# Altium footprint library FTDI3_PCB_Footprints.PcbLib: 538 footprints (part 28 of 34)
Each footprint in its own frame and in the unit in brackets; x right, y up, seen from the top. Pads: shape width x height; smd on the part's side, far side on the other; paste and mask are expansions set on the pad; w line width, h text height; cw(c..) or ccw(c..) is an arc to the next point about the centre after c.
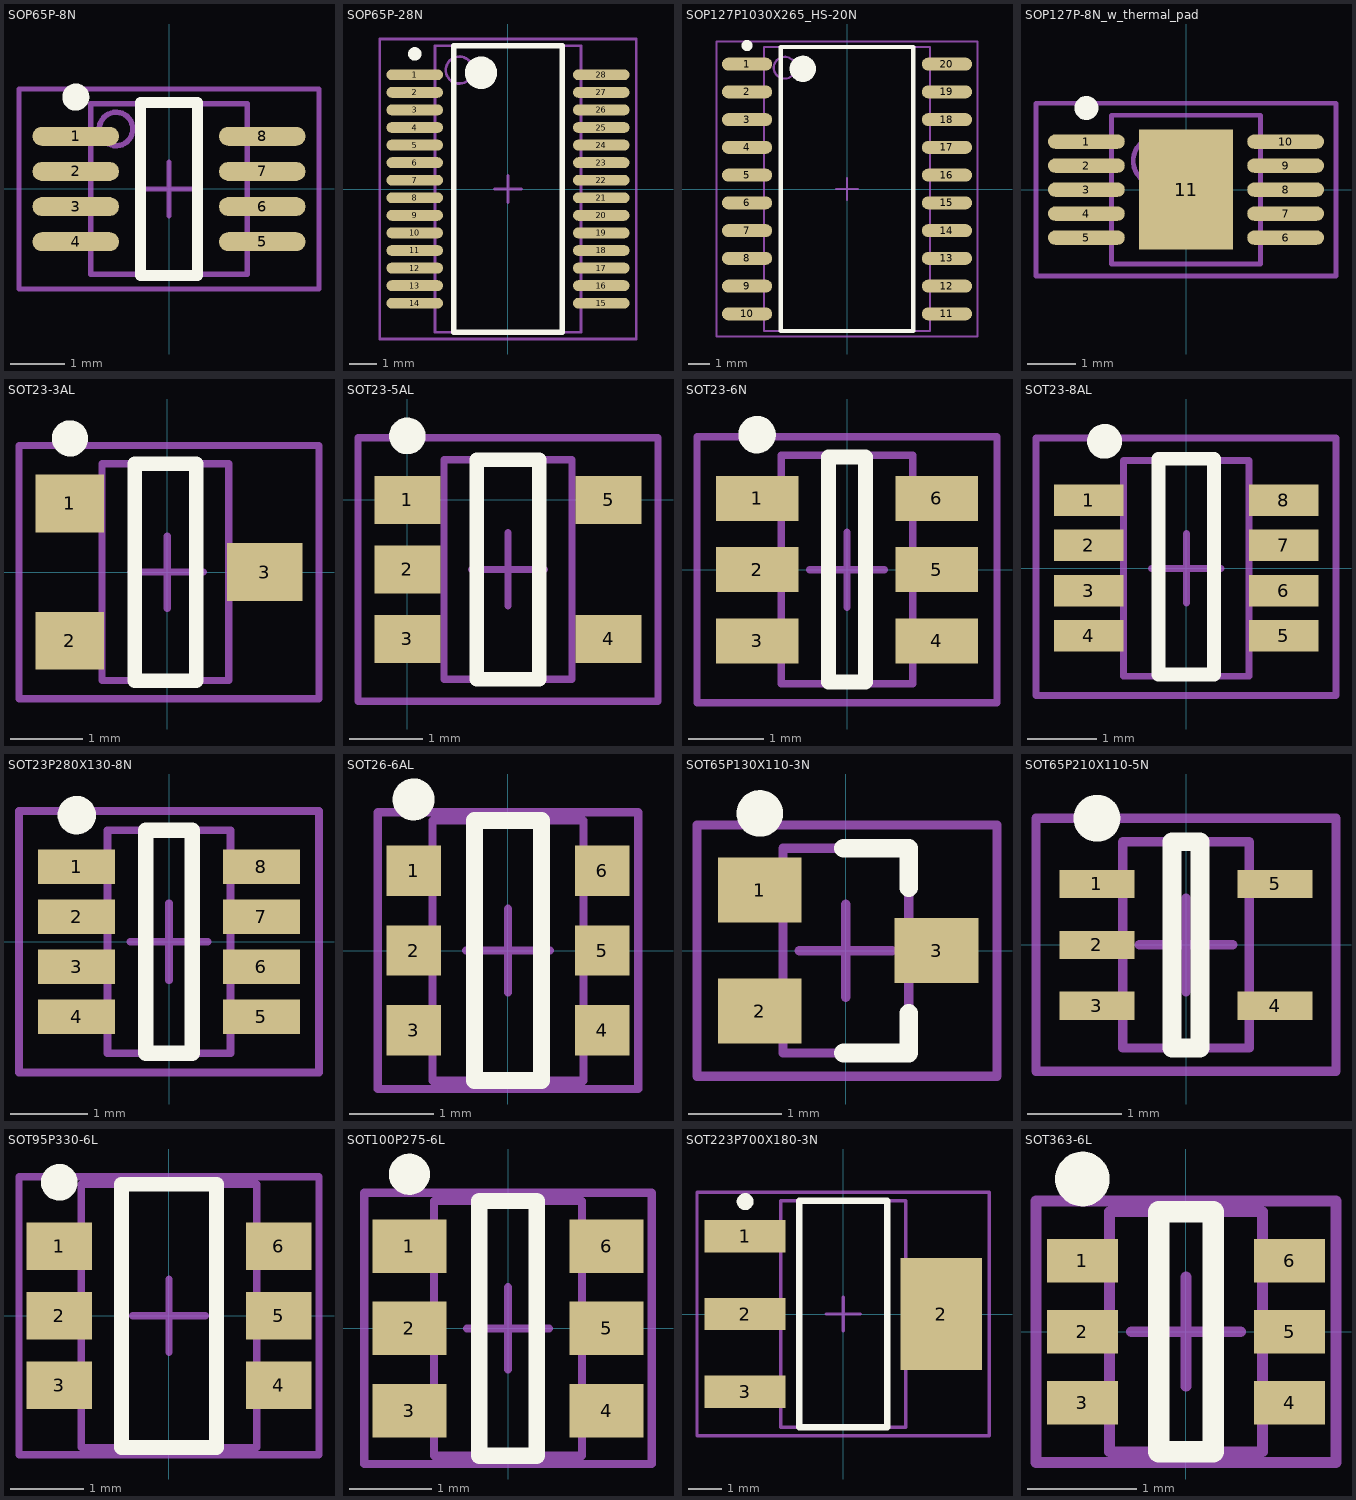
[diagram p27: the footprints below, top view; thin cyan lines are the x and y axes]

## SOP65P-8N [mm] "SOP, 8-Leads, Body 3.2x2.9mm (max), Pitch 0.65mm, IPC Medium Density"
height 1.3
pads (8):
  oval 1.6x0.35 smd: 1(-1.725,0.975) 2(-1.725,0.325) 3(-1.725,-0.325) 4(-1.725,-0.975) 5(1.725,-0.975) 6(1.725,-0.325) 7(1.725,0.325) 8(1.725,0.975)
Top Overlay:
  circle w0.25: c-1.725,1.7 r0.125
  lines w0.2: -0.525,-1.6 -0.525,1.6 0.525,1.6 0.525,-1.6 -0.525,-1.6
M13_Assembly_Info:
  circle w0.1: c-0.98,1.11 r0.31
  lines w0.1: -1.45,-1.575 -1.45,1.575 1.45,1.575 1.45,-1.575 -1.45,-1.575
M15_Country_Yard:
  lines w0.1: -0.5,0 0.5,0 ; 0,-0.5 0,0.5 ; -2.775,-1.85 -2.775,1.85 2.775,1.85 2.775,-1.85 -2.775,-1.85
3D body: height 1.3, standoff 0.1, extent -1.45,-1.575 1.45,1.575

## SOP65P-28N [mm] "SOP, 28-Leads, Body 10.2x5.3mm, Pitch 0.65mm, IPC Medium Density"
height 2
pads (28):
  oval 2.1x0.4 smd: 1(-3.45,4.225) 2(-3.45,3.575) 3(-3.45,2.925) 4(-3.45,2.275) 5(-3.45,1.625) 6(-3.45,0.975) 7(-3.45,0.325) 8(-3.45,-0.325) 9(-3.45,-0.975) 10(-3.45,-1.625) 11(-3.45,-2.275) 12(-3.45,-2.925) 13(-3.45,-3.575) 14(-3.45,-4.225) 15(3.45,-4.225) 16(3.45,-3.575) 17(3.45,-2.925) 18(3.45,-2.275) 19(3.45,-1.625) 20(3.45,-0.975) 21(3.45,-0.325) 22(3.45,0.325) 23(3.45,0.975) 24(3.45,1.625) 25(3.45,2.275) 26(3.45,2.925) 27(3.45,3.575) 28(3.45,4.225)
Top Overlay:
  circle w0.6: c-1,4.3 r0.3
  circle w0.25: c-3.45,5 r0.125
  lines w0.2: -2,-5.3 2,-5.3 2,5.3 -2,5.3 -2,-5.3
M13_Assembly_Info:
  circle w0.1: c-1.8,4.4 r0.5
  lines w0.1: -2.7,-5.3 2.7,-5.3 2.7,5.3 -2.7,5.3 -2.7,-5.3
M15_Country_Yard:
  lines w0.1: -0.5,0 0.5,0 ; 0,-0.5 0,0.5 ; -4.75,-5.55 4.75,-5.55 4.75,5.55 -4.75,5.55 -4.75,-5.55
3D body: height 2, standoff 0, extent -2.7,-5.3 2.7,5.3

## SOP127P1030X265_HS-20N [mm] "SOP, 20-Leads, Body 13.0x7.6mm (max), Pitch 1.27mm, IPC Medium Density"
height 2.65
pads (20):
  oval 2.3x0.6 smd: 1(-4.575,5.715) 2(-4.575,4.445) 3(-4.575,3.175) 4(-4.575,1.905) 5(-4.575,0.635) 6(-4.575,-0.635) 7(-4.575,-1.905) 8(-4.575,-3.175) 9(-4.575,-4.445) 10(-4.575,-5.715) 11(4.575,-5.715) 12(4.575,-4.445) 13(4.575,-3.175) 14(4.575,-1.905) 15(4.575,-0.635) 16(4.575,0.635) 17(4.575,1.905) 18(4.575,3.175) 19(4.575,4.445) 20(4.575,5.715)
Top Overlay:
  circle w0.25: c-4.575,6.565 r0.125
  circle w0.6: c-2.025,5.5 r0.3
  lines w0.2: -3.025,-6.5 -3.025,6.5 3.025,6.5 3.025,-6.5 -3.025,-6.5
M13_Assembly_Info:
  circle w0.1: c-2.85,5.55 r0.5
  lines w0.1: -3.8,-6.5 -3.8,6.5 3.8,6.5 3.8,-6.5 -3.8,-6.5
M15_Country_Yard:
  lines w0.1: -0.5,0 0.5,0 ; 0,-0.5 0,0.5 ; -5.975,-6.75 -5.975,6.75 5.975,6.75 5.975,-6.75 -5.975,-6.75
3D body: height 2.65, standoff 0.3, extent -3.8,-6.5 3.8,6.5

## SOP127P-8N_w_thermal_pad [mm]
height 1.1
pads (11):
  oval 1.6x0.3 smd: 1(-2.075,1) 2(-2.075,0.5) 3(-2.075,0) 4(-2.075,-0.5) 5(-2.075,-1) 6(2.075,-1) 7(2.075,-0.5) 8(2.075,0) 9(2.075,0.5) 10(2.075,1)
  rect 1.95x2.5 smd: 11(0,0)
Top Overlay:
  circle w0.25: c-2.075,1.7 r0.125
M13_Assembly_Info:
  circle w0.1: c-0.6,0.6 r0.5
  lines w0.1: -1.55,-1.55 1.55,-1.55 1.55,1.55 -1.55,1.55 -1.55,-1.55
M15_Country_Yard:
  lines w0.1: -0.5,0 0.5,0 ; 0,-0.5 0,0.5 ; -3.125,-1.8 3.125,-1.8 3.125,1.8 -3.125,1.8 -3.125,-1.8
3D body: height 1.1, standoff 0.2, extent -1.55,-1.55 1.55,1.55

## SOT23-3AL [mm] "SOT23 SMT Package"
pads (3):
  rect 0.95x0.8 smd: 1(-1.35,0.95) 2(-1.35,-0.95)
  rect 1.05x0.8 smd: 3(1.35,0)
Top Overlay:
  circle w0.25: c-1.345,1.85 r0.125
  lines w0.2: -0.45,-1.5 0.4,-1.5 0.4,1.5 -0.45,1.5 -0.45,-1.5
M13_Assembly_Info:
  lines w0.1: -0.9,-1.5 -0.9,1.5 0.85,1.5 0.85,-1.5 -0.9,-1.5
M15_Country_Yard:
  lines w0.1: -0.5,0 0.5,0 ; 0,-0.5 0,0.5 ; -2.05,-1.75 -2.05,1.75 2.1,1.75 2.1,-1.75 -2.05,-1.75
3D body: height 0.95, standoff -0.07, extent -1.242,-1.467 1.234,1.453

## SOT23-5AL [mm] "SOT23, 5-Leads, Body 2.9x1.6mm, Pitch 0.95mm, Lead Span 2.8mm"
height 1.45
pads (5):
  rect 0.9x0.65 smd: 1(0,0) 2(0,-0.95) 3(0,-1.9) 4(2.75,-1.9) 5(2.75,0)
Top Overlay:
  circle w0.25: c0,0.875 r0.125
  lines w0.2: 0.95,-2.45 1.8,-2.45 1.8,0.55 0.95,0.55 0.95,-2.45
M13_Assembly_Info:
  lines w0.1: 0.5,-2.45 0.5,0.55 2.25,0.55 2.25,-2.45 0.5,-2.45
M15_Country_Yard:
  lines w0.1: 0.875,-0.95 1.875,-0.95 ; 1.375,-1.45 1.375,-0.45 ; -0.675,-2.75 -0.675,0.85 3.425,0.85 3.425,-2.75 -0.675,-2.75
3D body: height 0, standoff 0, extent 0.5,-2.45 2.25,0.55

## SOT23-6N [mm] "SOT23, 6-Leads, Body 3.0x3.0mm (max), Pitch 0.95mm, IPC Medium Density"
height 1.45
pads (6):
  rect 1.1x0.6 smd: 1(-1.2,0.95) 2(-1.2,0) 3(-1.2,-0.95) 4(1.2,-0.95) 5(1.2,0) 6(1.2,0.95)
Top Overlay:
  circle w0.25: c-1.2,1.8 r0.125
  lines w0.2: -0.25,-1.5 0.25,-1.5 0.25,1.5 -0.25,1.5 -0.25,-1.5
M13_Assembly_Info:
  lines w0.1: -0.875,-1.525 -0.875,1.525 0.875,1.525 0.875,-1.525 -0.875,-1.525
M15_Country_Yard:
  lines w0.1: -0.5,0 0.5,0 ; 0,-0.5 0,0.5 ; -2,-1.775 -2,1.775 2,1.775 2,-1.775 -2,-1.775
3D body: height 1.45, standoff 0.1, extent -0.875,-1.525 0.875,1.525

## SOT23-8AL [mm] "SOT23 8-PIN 0.65mm PITCH"
height 1.45
pads (8):
  rect 1x0.45 smd: 1(-1.4,0.98) 2(-1.4,0.33) 3(-1.4,-0.32) 4(-1.4,-0.97) 5(1.4,-0.97) 6(1.4,-0.32) 7(1.4,0.33) 8(1.4,0.98)
Top Overlay:
  circle w0.25: c-1.175,1.825 r0.125
  lines w0.2: -0.4,-1.525 0.4,-1.525 0.4,1.575 -0.4,1.575 -0.4,-1.525
M13_Assembly_Info:
  lines w0.1: -0.9,-1.55 -0.9,1.55 0.9,1.55 0.9,-1.55 -0.9,-1.55
M15_Country_Yard:
  lines w0.1: -0.5,0 0.5,0 ; 0,-0.5 0,0.5 ; -2.16,-1.825 -2.16,1.875 2.15,1.875 2.15,-1.825 -2.16,-1.825
3D body: height 1.1, standoff 0, extent -0.9,-1.575 0.9,1.525

## SOT23P280X130-8N [mm] "SOT23, 8-Leads, Body 2.9x2.8mm (max), Pitch 0.65mm, IPC Medium Density"
height 1.3
pads (8):
  rect 1x0.45 smd: 1(-1.2,0.975) 2(-1.2,0.325) 3(-1.2,-0.325) 4(-1.2,-0.975) 5(1.2,-0.975) 6(1.2,-0.325) 7(1.2,0.325) 8(1.2,0.975)
Top Overlay:
  circle w0.25: c-1.2,1.645 r0.125
  lines w0.2: -0.3,-1.45 -0.3,1.45 0.3,1.45 0.3,-1.45 -0.3,-1.45
M13_Assembly_Info:
  lines w0.1: -0.8,-1.45 0.8,-1.45 0.8,1.45 -0.8,1.45 -0.8,-1.45
M15_Country_Yard:
  lines w0.1: -0.5,0 0.5,0 ; 0,-0.5 0,0.5 ; -1.95,-1.7 1.95,-1.7 1.95,1.7 -1.95,1.7 -1.95,-1.7
3D body: height 1.3, standoff 0.15, extent -0.8,-1.45 0.8,1.45

## SOT26-6AL [mm] "SOT23, 6-Leads, Body 2.9x1.6mm, Pitch 0.95mm, Lead Span 2.5mm, IPC High Density"
height 1.1
pads (6):
  rect 0.65x0.6 smd: 1(-1.125,0.95) 2(-1.125,0) 3(-1.125,-0.95) 4(1.125,-0.95) 5(1.125,0) 6(1.125,0.95)
Top Overlay:
  circle w0.25: c-1.125,1.8 r0.125
  lines w0.2: -0.4,-1.55 0.4,-1.55 0.4,1.55 -0.4,1.55 -0.4,-1.55
M13_Assembly_Info:
  lines w0.1: -0.9,-1.55 -0.9,1.55 0.9,1.55 0.9,-1.55 -0.9,-1.55
M15_Country_Yard:
  lines w0.1: -0.5,0 0.5,0 ; 0,-0.5 0,0.5 ; -1.55,-1.65 -1.55,1.65 1.55,1.65 1.55,-1.65 -1.55,-1.65
3D body: height 1.1, standoff 0, extent -0.9,-1.55 0.9,1.55

## SOT65P130X110-3N [mm] "SOT23, 3-Leads, Body 2.2x1.4mm (max), Pitch 0.65mm, IPC Medium Density"
height 1.1
pads (3):
  rect 0.9x0.7 smd: 1(-0.925,0.65) 2(-0.925,-0.65) 3(0.975,0)
Top Overlay:
  circle w0.25: c-0.925,1.475 r0.125
  lines w0.2: -0.025,-1.1 0.675,-1.1 0.675,-0.675 ; -0.025,1.1 0.675,1.1 0.675,0.675
M13_Assembly_Info:
  lines w0.1: -0.675,-1.1 -0.675,1.1 0.675,1.1 0.675,-1.1 -0.675,-1.1
M15_Country_Yard:
  lines w0.1: -0.5,0 0.5,0 ; 0,-0.5 0,0.5 ; -1.6,-1.35 -1.6,1.35 1.625,1.35 1.625,-1.35 -1.6,-1.35
3D body: height 1.1, standoff 0.05, extent -0.675,-1.1 0.675,1.1

## SOT65P210X110-5N [mm] "SOT23, 5-Leads, Body 2.2x2.2mm (max), Pitch 0.65mm, IPC Medium Density"
height 1.1
pads (5):
  rect 0.8x0.3 smd: 1(-0.95,0.65) 2(-0.95,0) 3(-0.95,-0.65) 4(0.95,-0.65) 5(0.95,0.65)
Top Overlay:
  circle w0.25: c-0.95,1.35 r0.125
  lines w0.2: -0.15,-1.1 -0.15,1.1 0.15,1.1 0.15,-1.1 -0.15,-1.1
M13_Assembly_Info:
  lines w0.1: -0.675,-1.1 0.675,-1.1 0.675,1.1 -0.675,1.1 -0.675,-1.1
M15_Country_Yard:
  lines w0.1: -0.5,0 0.5,0 ; 0,-0.5 0,0.5 ; -1.6,-1.35 1.6,-1.35 1.6,1.35 -1.6,1.35 -1.6,-1.35
3D body: height 1.1, standoff 0.05, extent -0.675,-1.1 0.675,1.1

## SOT95P330-6L [mm] "Small Outline, 6-Leads, Body 3.4x2.2mm, Pitch 0.95mm, Lead Span 3.3mm, IPC High Density"
height 1.4
pads (6):
  rect 0.9x0.65 smd: 1(-1.5,0.95) 2(-1.5,0) 3(-1.5,-0.95) 4(1.5,-0.95) 5(1.5,0) 6(1.5,0.95)
Top Overlay:
  circle w0.25: c-1.5,1.825 r0.125
  lines w0.2: -0.65,-1.8 -0.65,1.8 0.65,1.8 0.65,-1.8 -0.65,-1.8
M13_Assembly_Info:
  lines w0.1: -1.2,-1.8 1.2,-1.8 1.2,1.8 -1.2,1.8 -1.2,-1.8
M15_Country_Yard:
  lines w0.1: -0.5,0 0.5,0 ; 0,-0.5 0,0.5 ; -2.05,-1.9 2.05,-1.9 2.05,1.9 -2.05,1.9 -2.05,-1.9
3D body: height 1.4, standoff 0, extent -1.2,-1.8 1.2,1.8

## SOT100P275-6L [mm] "SOT23, 6-Leads, Body 3x1.5mm, Pitch 1mm, Lead Span 2.7mm, IPC High Density"
height 1.1
pads (6):
  rect 0.9x0.65 smd: 1(-1.2,1) 2(-1.2,0) 3(-1.2,-1) 4(1.2,-1) 5(1.2,0) 6(1.2,1)
Top Overlay:
  circle w0.25: c-1.2,1.875 r0.125
  lines w0.2: -0.35,-1.55 -0.35,1.55 0.35,1.55 0.35,-1.55 -0.35,-1.55
M13_Assembly_Info:
  lines w0.1: -0.9,-1.55 0.9,-1.55 0.9,1.55 -0.9,1.55 -0.9,-1.55
M15_Country_Yard:
  lines w0.1: -0.5,0 0.5,0 ; 0,-0.5 0,0.5 ; -1.75,-1.65 1.75,-1.65 1.75,1.65 -1.75,1.65 -1.75,-1.65
3D body: height 1.1, standoff 0, extent -0.9,-1.55 0.9,1.55

## SOT223P700X180-3N [mm] "SOT223, 4-Leads, Body 6.7x7.3mm (max), Pitch 2.30mm, IPC Medium Density"
height 1.8
pads (4):
  rect 2.4x0.95 smd: 1(-2.9,2.3) 2(-2.9,0) 3(-2.9,-2.3)
  rect 2.4x3.3 smd: 2(2.9,0)
Top Overlay:
  circle w0.25: c-2.9,3.325 r0.125
  lines w0.2: -1.3,-3.35 -1.3,3.35 1.3,3.35 1.3,-3.35 -1.3,-3.35
M13_Assembly_Info:
  lines w0.1: -1.85,-3.35 -1.85,3.35 1.85,3.35 1.85,-3.35 -1.85,-3.35
M15_Country_Yard:
  lines w0.1: -0.5,0 0.5,0 ; 0,-0.5 0,0.5 ; -4.325,-3.6 -4.325,3.6 4.325,3.6 4.325,-3.6 -4.325,-3.6
3D body: height 1.8, standoff 0.02, extent -1.85,-3.35 1.85,3.35

## SOT363-6L [mm] "SOT363, 6-Leads, Body 2x1.3mm, Pitch 0.65mm, Lead Span 2.1mm, IPC High Density"
height 1
pads (6):
  rect 0.65x0.4 smd: 1(-0.95,0.65) 2(-0.95,0) 3(-0.95,-0.65) 4(0.95,-0.65) 5(0.95,0) 6(0.95,0.65)
Top Overlay:
  circle w0.25: c-0.95,1.4 r0.125
  lines w0.2: -0.25,-1.1 0.25,-1.1 0.25,1.1 -0.25,1.1 -0.25,-1.1
M13_Assembly_Info:
  lines w0.1: -0.7,-1.1 -0.7,1.1 0.7,1.1 0.7,-1.1 -0.7,-1.1
M15_Country_Yard:
  lines w0.1: -0.5,0 0.5,0 ; 0,-0.5 0,0.5 ; -1.375,-1.2 -1.375,1.2 1.375,1.2 1.375,-1.2 -1.375,-1.2
3D body: height 1, standoff 0, extent -0.7,-1.1 0.7,1.1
